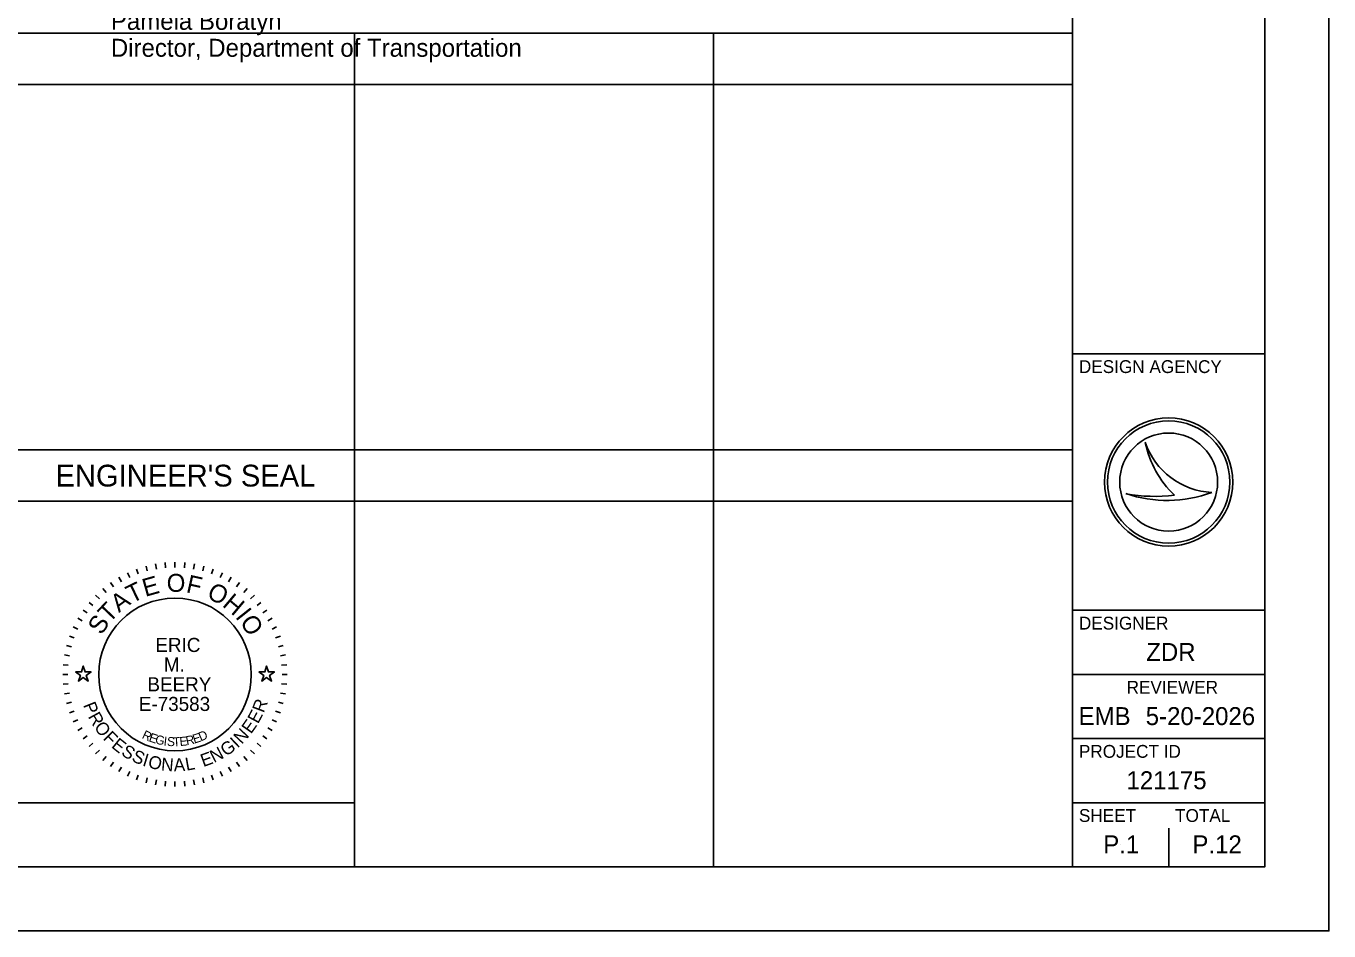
# Model space of a CAD drawing. Extents: x -6.6 to 34, y 0 to 22.
# Drawn here: x 23.84 to 34, y 0 to 7.06 of the extents above; entities that cross this region are included whole.
import ezdxf

# ---------------------------------------------------------------- set-up
doc = ezdxf.new("R2010")
doc.units = 0
for name, color, linetype in [('SH_Border', 7, 'Continuous'), ('SH_Cut_Line', 7, 'Continuous'), ('SH_Data', 7, 'Continuous'), ('SH_Seal', 7, 'Continuous'), ('SH_Text', 7, 'Continuous')]:
    doc.layers.add(name, color=color, linetype=linetype)

msp = doc.modelspace()

# ---------------------------------------------------------------- linework, layer by layer
at = {"layer": 'SH_Border'}
for p, q in [((32, 0.5), (32, 21.5)), ((32, 4.5), (33.5, 4.5)), ((32, 2.5), (33.5, 2.5)), ((32, 2), (33.5, 2)), ((32, 1.5), (33.5, 1.5)), ((32, 1), (33.5, 1))]:
    msp.add_line(p, q, dxfattribs=at)
msp.add_lwpolyline([(1.5, 21.5), (33.5, 21.5), (33.5, 0.5), (1.5, 0.5)], close=True, dxfattribs=at)
at = {"layer": 'SH_Cut_Line'}
msp.add_lwpolyline([(0, 0), (34, 0), (34, 22), (0, 22)], close=True, dxfattribs=at)
at = {"layer": 'SH_Data'}
for p, q in [((23.6, 6.6), (26.4, 6.6)), ((26.4, 6.6), (29.2, 6.6)), ((29.2, 6.6), (32, 6.6)), ((32.567, 3.81), (32.567, 3.81)), ((23.6, 3.75), (26.4, 3.75)), ((26.4, 3.75), (26.4, 0.5)), ((32.75, 3.5), (32.75, 3.5)), ((32.417, 3.41), (32.417, 3.41)), ((33.087, 3.419), (33.087, 3.419)), ((23.6, 3.35), (26.4, 3.35)), ((23.6, 3.35), (26.4, 3.35)), ((26.4, 3.35), (29.2, 3.35)), ((29.2, 3.35), (32, 3.35)), ((32.75, 0.5), (32.75, 0.8)), ((32.375, 0.675), (32.375, 0.675)), ((23.6, 0.5), (26.4, 0.5))]:
    msp.add_line(p, q, dxfattribs=at)
for points in [[(26.4, 7), (23.6, 7), (23.6, 3.75), (26.4, 3.75)], [(29.2, 7), (26.4, 7), (26.4, 3.75), (29.2, 3.75)], [(32, 7), (29.2, 7), (29.2, 3.75), (32, 3.75)], [(26.4, 3.75), (23.6, 3.75), (23.6, 0.5), (26.4, 0.5)], [(29.2, 3.75), (26.4, 3.75), (26.4, 0.5), (29.2, 0.5)], [(32, 3.75), (29.2, 3.75), (29.2, 0.5), (32, 0.5)], [(23.6, 0.5), (23.6, 1), (26.4, 1), (26.4, 0.5)]]:
    msp.add_lwpolyline(points, close=True, dxfattribs=at)
for radius in [0.5, 0.477, 0.477, 0.382]:
    msp.add_circle((32.75, 3.5), radius, dxfattribs=at)
for centre, radius, start, end in [((33.116, 3.998), 0.58, 198.9257, 198.9319), ((33.347, 3.97), 0.796, 191.6379, 191.6421), ((33.116, 3.998), 0.58, 198.9319, 267.1657), ((33.347, 3.97), 0.796, 191.6421, 226.0947), ((32.739, 4.37), 1.013, 251.4576, 290.0832), ((32.648, 4.654), 1.266, 259.4964, 259.4995), ((32.739, 4.37), 1.013, 251.4527, 251.4576), ((32.648, 4.654), 1.266, 259.4995, 276.6672)]:
    msp.add_arc(centre, radius, start, end, dxfattribs=at)
at = {"layer": 'SH_Seal'}
for p, q in [((24.848, 2.862), (24.855, 2.822)), ((24.924, 2.872), (24.927, 2.832)), ((25, 2.875), (25, 2.835)), ((25.076, 2.872), (25.073, 2.832)), ((25.152, 2.862), (25.145, 2.822)), ((24.563, 2.758), (24.583, 2.723)), ((24.63, 2.793), (24.647, 2.757)), ((24.701, 2.822), (24.714, 2.785)), ((24.774, 2.845), (24.784, 2.807)), ((25.226, 2.845), (25.216, 2.807)), ((25.299, 2.822), (25.286, 2.785)), ((25.37, 2.793), (25.353, 2.757)), ((25.437, 2.758), (25.417, 2.723)), ((24.438, 2.67), (24.463, 2.64)), ((24.498, 2.717), (24.521, 2.684)), ((25.502, 2.717), (25.479, 2.684)), ((25.562, 2.67), (25.537, 2.64)), ((24.33, 2.562), (24.36, 2.537)), ((24.381, 2.619), (24.41, 2.59)), ((25.619, 2.619), (25.59, 2.59)), ((25.67, 2.562), (25.64, 2.537)), ((24.283, 2.502), (24.316, 2.479)), ((25.717, 2.502), (25.684, 2.479)), ((24.207, 2.37), (24.243, 2.353)), ((24.242, 2.438), (24.277, 2.418)), ((25.758, 2.438), (25.723, 2.418)), ((25.793, 2.37), (25.757, 2.353)), ((24.178, 2.299), (24.215, 2.286)), ((25.822, 2.299), (25.785, 2.286)), ((24.138, 2.152), (24.178, 2.145)), ((24.155, 2.226), (24.193, 2.216)), ((25.845, 2.226), (25.807, 2.216)), ((25.862, 2.152), (25.822, 2.145)), ((24.128, 2.076), (24.168, 2.073)), ((25.872, 2.076), (25.832, 2.073)), ((24.125, 2), (24.165, 2)), ((25.875, 2), (25.835, 2)), ((24.128, 1.924), (24.168, 1.927)), ((24.138, 1.848), (24.178, 1.855)), ((25.862, 1.848), (25.822, 1.855)), ((25.872, 1.924), (25.832, 1.927)), ((24.155, 1.774), (24.193, 1.784)), ((25.845, 1.774), (25.807, 1.784)), ((24.178, 1.701), (24.215, 1.714)), ((24.207, 1.63), (24.243, 1.647)), ((25.793, 1.63), (25.757, 1.647)), ((25.822, 1.701), (25.785, 1.714)), ((24.242, 1.563), (24.277, 1.583)), ((25.758, 1.563), (25.723, 1.583)), ((24.283, 1.498), (24.316, 1.521)), ((24.33, 1.438), (24.36, 1.463)), ((25.67, 1.438), (25.64, 1.463)), ((25.717, 1.498), (25.684, 1.521)), ((24.381, 1.381), (24.41, 1.41)), ((24.438, 1.33), (24.463, 1.36)), ((25.562, 1.33), (25.537, 1.36)), ((25.619, 1.381), (25.59, 1.41)), ((24.498, 1.283), (24.521, 1.316)), ((24.563, 1.242), (24.583, 1.277)), ((24.63, 1.207), (24.647, 1.243)), ((25.37, 1.207), (25.353, 1.243)), ((25.437, 1.242), (25.417, 1.277)), ((25.502, 1.283), (25.479, 1.316)), ((24.701, 1.178), (24.714, 1.215)), ((24.774, 1.155), (24.784, 1.193)), ((24.848, 1.138), (24.855, 1.178)), ((24.924, 1.128), (24.927, 1.168)), ((25, 1.125), (25, 1.165)), ((25.076, 1.128), (25.073, 1.168)), ((25.152, 1.138), (25.145, 1.178)), ((25.226, 1.155), (25.216, 1.193)), ((25.299, 1.178), (25.286, 1.215))]:
    msp.add_line(p, q, dxfattribs=at)
for points in [[(24.224, 2.02), (24.271, 2.02), (24.285, 2.065), (24.299, 2.02), (24.346, 2.02), (24.308, 1.992), (24.323, 1.948), (24.285, 1.975), (24.247, 1.948), (24.262, 1.992)], [(25.654, 2.02), (25.701, 2.02), (25.715, 2.065), (25.729, 2.02), (25.776, 2.02), (25.738, 1.992), (25.753, 1.948), (25.715, 1.975), (25.677, 1.948), (25.692, 1.992)]]:
    msp.add_lwpolyline(points, close=True, dxfattribs=at)
msp.add_circle((25, 2), 0.595, dxfattribs=at)

# ---------------------------------------------------------------- texts
at = {"layer": 'SH_Data'}
for s, height, p in [('DESIGN AGENCY', 0.1, (32.05, 4.35)), ("ENGINEER'S SEAL", 0.17, (24.068, 3.465)), ('DESIGNER', 0.1, (32.05, 2.35)), ('ZDR', 0.14, (32.575, 2.105)), ('REVIEWER', 0.1, (32.422, 1.85)), ('EMB', 0.14, (32.047, 1.605)), ('5-20-2026', 0.14, (32.571, 1.605)), ('PROJECT ID', 0.1, (32.05, 1.35)), ('121175', 0.14, (32.421, 1.105)), ('SHEET', 0.1, (32.05, 0.85)), ('TOTAL', 0.1, (32.8, 0.85)), ('P.1', 0.14, (32.24, 0.605)), ('P.12', 0.14, (32.935, 0.605))]:
    msp.add_text(s, height=height, dxfattribs=at).set_placement(p)
at = {"layer": 'SH_Seal'}
for s, height, rotation, p in [('E', 0.14, 15.7571, (24.768, 2.604)), ('O', 0.14, 359.7812, (24.935, 2.644)), ('F', 0.14, 347.4362, (25.081, 2.642)), ('T', 0.14, 25.7167, (24.662, 2.552)), ('O', 0.14, 332.2586, (25.24, 2.602)), ('T', 0.14, 46.4344, (24.488, 2.396)), ('A', 0.14, 36.4747, (24.563, 2.478)), ('H', 0.14, 319.9136, (25.363, 2.536)), ('S', 0.14, 57.1924, (24.428, 2.301)), ('I', 0.14, 308.367, (25.466, 2.448)), ('O', 0.14, 303.1491, (25.502, 2.409)), ('P', 0.1, 291.494, (24.282, 1.762)), ('E', 0.1, 61.9951, (25.648, 1.61)), ('R', 0.1, 69.2322, (25.692, 1.695)), ('R', 0.1, 298.7311, (24.319, 1.672)), ('O', 0.1, 306.4666, (24.365, 1.588)), ('E', 0.1, 54.758, (25.593, 1.531)), ('F', 0.1, 314.7068, (24.434, 1.498)), ('R', 0.07, 334.487, (24.737, 1.505)), ('E', 0.07, 341.04, (24.791, 1.48)), ('G', 0.07, 347.4752, (24.841, 1.462)), ('R', 0.07, 11.9184, (25.092, 1.447)), ('E', 0.07, 17.6836, (25.15, 1.46)), ('D', 0.07, 23.3052, (25.201, 1.477)), ('N', 0.1, 47.0224, (25.52, 1.451)), ('E', 0.1, 321.4393, (24.498, 1.435)), ('S', 0.1, 328.6764, (24.574, 1.375)), ('I', 0.07, 353.7858, (24.909, 1.447)), ('S', 0.07, 356.8926, (24.936, 1.443)), ('T', 0.07, 3.0061, (24.986, 1.439)), ('E', 0.07, 6.0117, (25.039, 1.441)), ('N', 0.1, 27.3113, (25.304, 1.308)), ('G', 0.1, 35.0469, (25.398, 1.357)), ('I', 0.1, 43.287, (25.487, 1.421)), ('S', 0.1, 335.9134, (24.656, 1.327)), ('I', 0.1, 343.1505, (24.741, 1.29)), ('O', 0.1, 346.8859, (24.784, 1.275)), ('N', 0.1, 355.1261, (24.889, 1.252)), ('A', 0.1, 2.8617, (24.992, 1.244)), ('L', 0.1, 10.0987, (25.089, 1.249)), ('E', 0.1, 20.0742, (25.221, 1.277))]:
    msp.add_text(s, height=height, rotation=rotation, dxfattribs=at).set_placement(p)
for s, p in [('ERIC', (24.847, 2.175)), ('M.', (24.913, 2.022)), ('BEERY', (24.785, 1.868)), ('E-73583', (24.718, 1.715))]:
    msp.add_text(s, height=0.11, dxfattribs=at).set_placement(p)
at = {"layer": 'SH_Text'}
for s, p in [('Pamela Boratyn', (24.5, 7.026)), ('Director, Department of Transportation', (24.5, 6.816))]:
    msp.add_text(s, height=0.14, dxfattribs=at).set_placement(p)

doc.saveas('drawing.dxf')
